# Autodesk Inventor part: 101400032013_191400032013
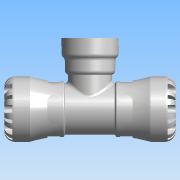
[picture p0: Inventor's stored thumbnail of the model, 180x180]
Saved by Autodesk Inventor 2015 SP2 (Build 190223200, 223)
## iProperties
Created: 2016-12
Part Number: 101400032013_191400032013
Material: PVC-Piping
Description: PLASSON TEE WITH THREADED FEMALE OFFTAKE 32X1.1/4" SERIES 1
Document SubType Name: Modeling
Designer: KIM
Mass: 664.223 g
Surface Area: 733.008 cm^2
Volume: 474.445 cm^3
Density: 1.4 g/cm^3
Appearance: Smooth - White
Author: KIM
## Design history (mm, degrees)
derived "1014.ipt"
feature "Solid1::1014.ipt"
tag "TaggingFeature1"
body "Solid1"
other parameters: "d1" = 22.68, "d2" = 32, "d4" = 58, "d8" = 49.3, "d13" = 7.2, "d14" = 7.2, "d15" = 0, "d17" = 360 deg, "d19" = 8 deg, "d20" = 0.64, "d21" = 0.64, "d22" = 8 deg, "d24" = 0, "d26" = 360 deg, "d33" = 5.8, "d43" = 45.24, "d51" = 0.58, "d54" = 11.2, "d55" = 7.04, "d57" = 14.112, "d58" = 0, "d74" = 0, "d77" = 2.66667, "d78" = 54, "d79" = 45.24, "d80" = 152, "d82" = 0.64, "d115" = 360 deg, "d139" = 7.2, "d140" = 0, "d142" = 360 deg, "d207" = 90 deg, "d228" = 9.52, "d247" = 1.16, "d248" = 3.24, "d266" = 0, "d268" = 38.952, "d270" = 5.8428, "d271" = 8, "d274" = 2.9214, "d275" = 63, "d276" = 3.8952, "d277" = 3.8952, "d278" = 3.8952, "d279" = 3.8952, "d281" = 0, "d282" = 24, "d_" = 32, "E_" = 58, "l_" = 54, "A_" = 63, "H_" = 152, "Rp_" = 38.952, "l_2" = 24, "d9" = 9, "d11" = 58
